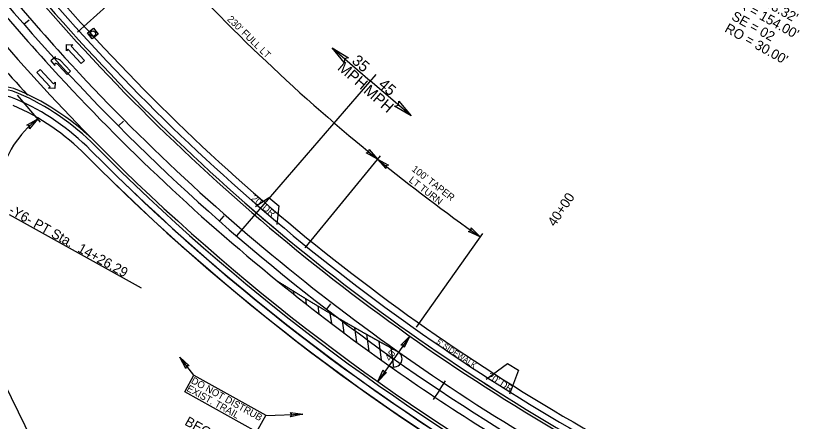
# Model space of a CAD drawing. Extents: x 1762196 to 1766326, y 709922 to 713142.
# Drawn here: x 1764158 to 1764730, y 711011 to 711303 of the extents above; entities that cross this region are included whole.
import ezdxf

# ---------------------------------------------------------------- set-up
doc = ezdxf.new("R2010")
doc.units = 0
for name, color, linetype in [('Default', 7, 'Continuous'), ('Old_Level_3', 7, 'Continuous'), ('Pattern 1', 7, 'Continuous'), ('Pattern 2', 7, 'Continuous'), ('Pattern 4', 7, 'Continuous'), ('Prop Conc 2ft 6in Curb and Gutter', 7, 'Continuous'), ('Prop Dimension', 7, 'Continuous'), ('Prop EOT', 7, 'Continuous'), ('Prop Horizontal Alignment', 7, 'Continuous'), ('Prop Horizontal Alignment Curve and Spiral Data', 7, 'Continuous'), ('Prop Horizontal Alignment Station Label', 7, 'Continuous'), ('Prop Horizontal Alignment Tick Label', 7, 'Continuous'), ('Prop Horizontal Alignment Tick Large', 7, 'Continuous'), ('Prop Horizontal Alignment Tick Small', 7, 'Continuous'), ('Prop Lane Arrow CELL', 7, 'Continuous'), ('Prop Lane Lines', 7, 'Continuous'), ('Prop Terminator CELL', 7, 'Continuous'), ('Scratch_Level_1', 7, 'Continuous')]:
    doc.layers.add(name, color=color, linetype=linetype)

msp = doc.modelspace()

# ---------------------------------------------------------------- linework, layer by layer
at = {"layer": 'Default'}
msp.add_lwpolyline([(1764217.34, 711289.92), (1764212.99, 711286.52), (1764209.58, 711290.87), (1764213.94, 711294.28)], close=True, dxfattribs=at)
msp.add_circle((1764213.44, 711290.35), 2.03, dxfattribs=at)
at = {"layer": 'Old_Level_3'}
for p, q in [((1764330.66, 711165.76), (1764340.1, 711172.15)), ((1764340.1, 711172.15), (1764347.29, 711166.37)), ((1764347.29, 711166.37), (1764345.86, 711152.77)), ((1764496.7, 711041.23), (1764512.06, 711052.7)), ((1764512.06, 711052.7), (1764519.98, 711047.82)), ((1764519.98, 711047.82), (1764513.58, 711030.5))]:
    msp.add_line(p, q, dxfattribs=at)
at = {"layer": 'Pattern 1'}
for centre, radius, start, end in [((1765296.46, 712280.56), 1468.5, 220.01407, 240.8436), ((1765296.46, 712280.56), 1473.5, 220.01407, 240.8436), ((1764142.65, 711207.92), 38.5, 66.4571, 153.5523), ((1764088.73, 711084.16), 173.5, 44.7299, 66.4571), ((1764088.73, 711084.16), 168.5, 44.7299, 66.4571), ((1765306.57, 712293.87), 1543.05, 224.81689, 240.93056), ((1765306.57, 712293.87), 1548.05, 224.8166, 240.93028)]:
    msp.add_arc(centre, radius, start, end, dxfattribs=at)
at = {"layer": 'Pattern 2'}
for centre, radius, start, end in [((1765296.46, 712280.56), 1468.5, 220.01407, 240.8436), ((1765296.46, 712280.56), 1473.5, 220.01407, 240.8436), ((1764142.65, 711207.92), 38.5, 66.4571, 153.5523), ((1764088.73, 711084.16), 173.5, 44.7299, 66.4571), ((1764088.73, 711084.16), 168.5, 44.7299, 66.4571), ((1765296.46, 712280.56), 1526.5, 224.72992, 240.8436), ((1765296.46, 712280.56), 1531.5, 224.72992, 240.8436)]:
    msp.add_arc(centre, radius, start, end, dxfattribs=at)
at = {"layer": 'Pattern 4'}
for p, q in [((1764328.71, 711163.48), (1764343.91, 711150.48)), ((1764495.09, 711038.69), (1764511.97, 711027.96))]:
    msp.add_line(p, q, dxfattribs=at)
at = {"layer": 'Prop Conc 2ft 6in Curb and Gutter'}
for centre, radius, start, end in [((1765296.46, 712280.56), 1478, 220.01407, 240.8436), ((1764142.65, 711207.92), 43, 66.4571, 153.5523), ((1764088.73, 711084.16), 178, 44.7299, 66.4571), ((1765296.46, 712280.56), 1522, 224.72992, 240.8436)]:
    msp.add_arc(centre, radius, start, end, dxfattribs=at)
at = {"layer": 'Prop Dimension'}
for p, q in [((1764265.83, 711348.82), (1764202.31, 711291.39)), ((1764385.79, 711280.05), (1764413.17, 711256.42)), ((1764417.13, 711261.01), (1764316.79, 711144.67)), ((1764442.55, 711231.09), (1764413.17, 711256.42)), ((1764175.68, 711226.67), (1764159.27, 711246.05)), ((1764420.23, 711202.34), (1764366.22, 711135.88)), ((1764494, 711146.36), (1764446.28, 711078.91)), ((1764441.66, 711072.38), (1764418.55, 711039.72)), ((1764286.28, 711044.12), (1764276.09, 711057.17)), ((1764337.94, 711015.18), (1764364.73, 711016.06))]:
    msp.add_line(p, q, dxfattribs=at)
msp.add_lwpolyline([(1764286.28, 711044.12), (1764338.01, 711015.32), (1764331.4, 711003.44), (1764279.67, 711032.25)], close=True, dxfattribs=at)
for centre, radius, start, end in [((1765296.46, 712280.56), 1392.37, 222.11492, 230.90027), ((1764218.76, 711170.06), 74, 127.3856, 167.5238), ((1765296.46, 712280.56), 1392.37, 230.90027, 234.71999)]:
    msp.add_arc(centre, radius, start, end, dxfattribs=at)
at = {"layer": 'Prop EOT'}
for centre, radius, start, end in [((1765296.46, 712280.56), 1480, 220.01407, 240.8436), ((1764142.65, 711207.92), 45, 66.4571, 153.5523), ((1764088.73, 711084.16), 180, 44.7299, 66.4571), ((1765296.46, 712280.56), 1520, 224.72992, 240.8436)]:
    msp.add_arc(centre, radius, start, end, dxfattribs=at)
at = {"layer": 'Prop Horizontal Alignment'}
msp.add_arc((1765296.46, 712280.56), 1500, 216.32502, 240.8436, dxfattribs=at)
at = {"layer": 'Prop Horizontal Alignment Station Label'}
for p, q in [((1764068.39, 711203.33), (1764195.76, 710944.38)), ((1764248.6, 711106.84), (1764153.33, 711159.89))]:
    msp.add_line(p, q, dxfattribs=at)
at = {"layer": 'Prop Horizontal Alignment Tick Large'}
for q in [(1764467.51, 711040.04), (1764467.51, 711040.04), (1764458.62, 711026.73), (1764458.62, 711026.73)]:
    msp.add_line((1764463.06, 711033.38), q, dxfattribs=at)
at = {"layer": 'Prop Horizontal Alignment Tick Small'}
for p, q in [((1764163.87, 711297.08), (1764167.64, 711300.36)), ((1764163.87, 711297.08), (1764167.64, 711300.36)), ((1764231.9, 711223.82), (1764235.45, 711227.34)), ((1764231.9, 711223.82), (1764235.45, 711227.34)), ((1764304.66, 711155.24), (1764307.97, 711159)), ((1764304.66, 711155.24), (1764307.97, 711159)), ((1764381.83, 711091.67), (1764384.88, 711095.64)), ((1764381.83, 711091.67), (1764384.88, 711095.64))]:
    msp.add_line(p, q, dxfattribs=at)
at = {"layer": 'Prop Lane Arrow CELL'}
for p, q in [((1764194.37, 711278.09), (1764194.51, 711282.51)), ((1764195.47, 711279.11), (1764194.37, 711278.09)), ((1764194.51, 711282.51), (1764199, 711282.36)), ((1764204.96, 711268.82), (1764195.47, 711279.11)), ((1764199, 711282.36), (1764197.9, 711281.35)), ((1764197.9, 711281.35), (1764207.39, 711271.05)), ((1764186.45, 711273.64), (1764183.17, 711270.7)), ((1764186.39, 711272.15), (1764186.45, 711273.64)), ((1764183.17, 711270.7), (1764186.17, 711267.35)), ((1764186.17, 711267.35), (1764186.24, 711268.83)), ((1764188.77, 711267.76), (1764194.95, 711261.01)), ((1764197.38, 711263.24), (1764190.26, 711271.02)), ((1764207.39, 711271.05), (1764204.96, 711268.82)), ((1764173.19, 711262.36), (1764175.62, 711264.6)), ((1764182.68, 711252.07), (1764173.19, 711262.36)), ((1764175.62, 711264.6), (1764185.11, 711254.3)), ((1764194.95, 711261.01), (1764197.38, 711263.24)), ((1764181.58, 711251.05), (1764182.68, 711252.07)), ((1764186.06, 711250.9), (1764181.58, 711251.05)), ((1764185.11, 711254.3), (1764186.21, 711255.32)), ((1764186.21, 711255.32), (1764186.06, 711250.9))]:
    msp.add_line(p, q, dxfattribs=at)
for centre, radius, start, end in [((1764186.36, 711265.57), 3.27, 42.4483, 92.1065), ((1764186.98, 711266.95), 5.25, 51.1244, 96.4361)]:
    msp.add_arc(centre, radius, start, end, dxfattribs=at)
at = {"layer": 'Prop Lane Lines'}
msp.add_line((1764347.47, 711111.18), (1764347.66, 711111.2), dxfattribs=at)
for radius, start, end in [(1494, 216.32502, 222.11492), (1506, 216.32502, 222.11492), (1520, 216.32502, 224.72992), (1532, 217.53858, 222.47123), (1494, 222.11492, 240.8436), (1506, 222.11492, 230.90027), (1506, 234.71999, 240.8436)]:
    msp.add_arc((1765296.46, 712280.56), radius, start, end, dxfattribs=at)
at = {"layer": 'Prop Terminator CELL'}
for points in [[(1764394.49, 711269.47), (1764385.79, 711280.05), (1764397.63, 711273), (1764394.76, 711272.31)], [(1764433.85, 711241.67), (1764442.55, 711231.09), (1764430.7, 711238.14), (1764433.58, 711238.83)], [(1764165.91, 711224.31), (1764173.83, 711228.86), (1764167.88, 711221.85), (1764167.74, 711223.82)], [(1764412.33, 711206.89), (1764418.33, 711200.01), (1764410.3, 711204.47), (1764412.2, 711204.99)], [(1764424.34, 711193.13), (1764418.33, 711200.01), (1764426.37, 711195.54), (1764424.46, 711195.03)], [(1764485.82, 711150.37), (1764492.27, 711143.91), (1764483.96, 711147.83), (1764485.82, 711148.47)], [(1764435.19, 711065.92), (1764441.66, 711072.38), (1764437.73, 711064.06), (1764437.09, 711065.93)], [(1764280.41, 711049.12), (1764276.09, 711057.17), (1764282.92, 711051.02), (1764280.95, 711050.94)], [(1764425.02, 711046.17), (1764418.55, 711039.72), (1764422.47, 711048.03), (1764423.11, 711046.17)], [(1764355.68, 711017.31), (1764364.73, 711016.06), (1764355.73, 711014.16), (1764356.83, 711015.8)]]:
    msp.add_lwpolyline(points, close=True, dxfattribs=at)
at = {"layer": 'Scratch_Level_1'}
for p, q in [((1764348.96, 711110.38), (1764349.03, 711109.92)), ((1764357.79, 711104.87), (1764358.1, 711102.63)), ((1764366.61, 711099.45), (1764367.16, 711095.47)), ((1764375.42, 711094.12), (1764376.2, 711088.44)), ((1764384.21, 711088.88), (1764385.22, 711081.53)), ((1764392.99, 711083.72), (1764394.23, 711074.74)), ((1764401.76, 711078.66), (1764403.22, 711068.06)), ((1764410.52, 711073.68), (1764412.19, 711061.5)), ((1764419.27, 711068.79), (1764421.15, 711055.05)), ((1764428, 711063.97), (1764429.91, 711050.05))]:
    msp.add_line(p, q, dxfattribs=at)
for centre, radius, start, end in [((1765296.46, 712280.56), 1506, 230.90027, 234.71999), ((1764430.1, 711056.05), 6, 234.72, 54.72)]:
    msp.add_arc(centre, radius, start, end, dxfattribs=at)
for points in [[(1764346.67, 711111.83), (1764347.25, 711111.46), (1764347.83, 711111.1), (1764348.4, 711110.73), (1764348.98, 711110.37), (1764349.56, 711110.01), (1764350.14, 711109.64), (1764350.72, 711109.28), (1764351.3, 711108.92), (1764351.87, 711108.55), (1764352.45, 711108.19), (1764353.03, 711107.83), (1764353.61, 711107.47), (1764354.19, 711107.11), (1764354.77, 711106.75), (1764355.35, 711106.39), (1764355.93, 711106.02), (1764356.51, 711105.66), (1764357.09, 711105.3), (1764357.67, 711104.94), (1764358.25, 711104.59), (1764358.83, 711104.23), (1764359.41, 711103.87), (1764359.99, 711103.51), (1764360.57, 711103.15), (1764361.15, 711102.79), (1764361.73, 711102.44), (1764362.31, 711102.08), (1764362.9, 711101.72), (1764363.48, 711101.36), (1764364.06, 711101.01), (1764364.64, 711100.65), (1764365.22, 711100.3), (1764365.8, 711099.94), (1764366.39, 711099.58), (1764366.97, 711099.23), (1764367.55, 711098.87), (1764368.13, 711098.52), (1764368.72, 711098.17), (1764369.3, 711097.81), (1764369.88, 711097.46), (1764370.46, 711097.1), (1764371.05, 711096.75), (1764371.63, 711096.4), (1764372.21, 711096.05), (1764372.8, 711095.69), (1764373.38, 711095.34), (1764373.97, 711094.99), (1764374.55, 711094.64), (1764375.13, 711094.29), (1764375.72, 711093.94), (1764376.3, 711093.59), (1764376.89, 711093.24), (1764377.47, 711092.89), (1764378.06, 711092.54), (1764378.64, 711092.19), (1764379.22, 711091.84), (1764379.81, 711091.49), (1764380.4, 711091.14), (1764380.98, 711090.79), (1764381.57, 711090.44), (1764382.15, 711090.1), (1764382.74, 711089.75), (1764383.32, 711089.4), (1764383.91, 711089.05), (1764384.5, 711088.71), (1764385.08, 711088.36), (1764385.67, 711088.02), (1764386.25, 711087.67), (1764386.84, 711087.33), (1764387.43, 711086.98), (1764388.01, 711086.64), (1764388.6, 711086.29), (1764389.19, 711085.95), (1764389.78, 711085.6)], [(1764389.78, 711085.6), (1764390.36, 711085.26), (1764390.95, 711084.92), (1764391.54, 711084.57), (1764392.13, 711084.23), (1764392.71, 711083.89), (1764393.3, 711083.54), (1764393.89, 711083.2), (1764394.48, 711082.86), (1764395.07, 711082.52), (1764395.65, 711082.18), (1764396.24, 711081.84), (1764396.83, 711081.5), (1764397.42, 711081.16), (1764398.01, 711080.82), (1764398.6, 711080.48), (1764399.19, 711080.14), (1764399.78, 711079.8), (1764400.37, 711079.46), (1764400.96, 711079.12), (1764401.55, 711078.78), (1764402.14, 711078.45), (1764402.73, 711078.11), (1764403.32, 711077.77), (1764403.91, 711077.43), (1764404.5, 711077.1), (1764405.09, 711076.76), (1764405.68, 711076.42), (1764406.27, 711076.09), (1764406.86, 711075.75), (1764407.45, 711075.42), (1764408.04, 711075.08), (1764408.63, 711074.75), (1764409.22, 711074.41), (1764409.81, 711074.08), (1764410.41, 711073.74), (1764411, 711073.41), (1764411.59, 711073.08), (1764412.18, 711072.74), (1764412.77, 711072.41), (1764413.37, 711072.08), (1764413.96, 711071.75), (1764414.55, 711071.41), (1764415.14, 711071.08), (1764415.74, 711070.75), (1764416.33, 711070.42), (1764416.92, 711070.09), (1764417.51, 711069.76), (1764418.11, 711069.43), (1764418.7, 711069.1), (1764419.29, 711068.77), (1764419.89, 711068.44), (1764420.48, 711068.11), (1764421.07, 711067.78), (1764421.67, 711067.45), (1764422.26, 711067.13), (1764422.86, 711066.8), (1764423.45, 711066.47), (1764424.04, 711066.14), (1764424.64, 711065.82), (1764425.23, 711065.49), (1764425.83, 711065.16), (1764426.42, 711064.84), (1764427.02, 711064.51), (1764427.61, 711064.19), (1764428.21, 711063.86), (1764428.8, 711063.54), (1764429.4, 711063.21), (1764429.99, 711062.89), (1764430.59, 711062.56), (1764431.19, 711062.24), (1764431.78, 711061.92), (1764432.38, 711061.59), (1764433.57, 711060.95)]]:
    msp.add_spline(points, degree=3, dxfattribs=at)

# ---------------------------------------------------------------- texts
at = {"layer": 'Prop Dimension'}
for s, height, rotation, p in [("230' FULL LT", 5, 315.6333, (1764309.85, 711300.3)), ('35', 8, 319.4764, (1764399.35, 711269.75)), ('MPH', 8, 319.4764, (1764389.03, 711264.89)), ('45', 8, 318.9697, (1764418.49, 711252.77)), ('MPH', 8, 318.9697, (1764407.79, 711248.3)), ("100' TAPER", 5, 322.2494, (1764442.63, 711191.85)), ('LT TURN', 5, 322.2494, (1764440.61, 711183.93)), ("20' DR", 5, 319.7116, (1764326.95, 711170.95)), ("5' SIDEWALK", 4, 326.2975, (1764460.45, 711067.35)), ("40'", 5, 54.72, (1764427.46, 711053.95)), ("20' DR", 5, 327.7808, (1764497.08, 711042.3)), ('DO NOT DISTRUB', 5, 330.8875, (1764283.73, 711038.79)), ('EXIST. TRAIL', 5, 330.8875, (1764280.56, 711033.11))]:
    msp.add_text(s, height=height, rotation=rotation, dxfattribs=at).set_placement(p)
at = {"layer": 'Prop Horizontal Alignment Curve and Spiral Data'}
for s, p in [('= 38%%d 11\' 33.2" (RT)', (1764708.42, 711338.54)), ("T = 53.32'", (1764682.45, 711318.32)), ("R = 154.00'", (1764677.59, 711309.59)), ('SE = 02', (1764672.72, 711300.85)), ("RO = 30.00'", (1764667.86, 711292.11))]:
    msp.add_text(s, height=7, rotation=330.8875, dxfattribs=at).set_placement(p)
at = {"layer": 'Prop Horizontal Alignment Station Label'}
for s, p in [('-Y6- PT Sta.  14+26.29', (1764152.33, 711161.15)), ('BEGIN CONSTRUCTION', (1764279.02, 711008.69))]:
    msp.add_text(s, height=7, rotation=330.8875, dxfattribs=at).set_placement(p)
at = {"layer": 'Prop Horizontal Alignment Tick Label'}
msp.add_text('40+00', height=7, rotation=56.2479, dxfattribs=at).set_placement((1764546.16, 711150.81))

doc.saveas('drawing.dxf')
